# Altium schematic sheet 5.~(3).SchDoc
size 420 x 297 mm
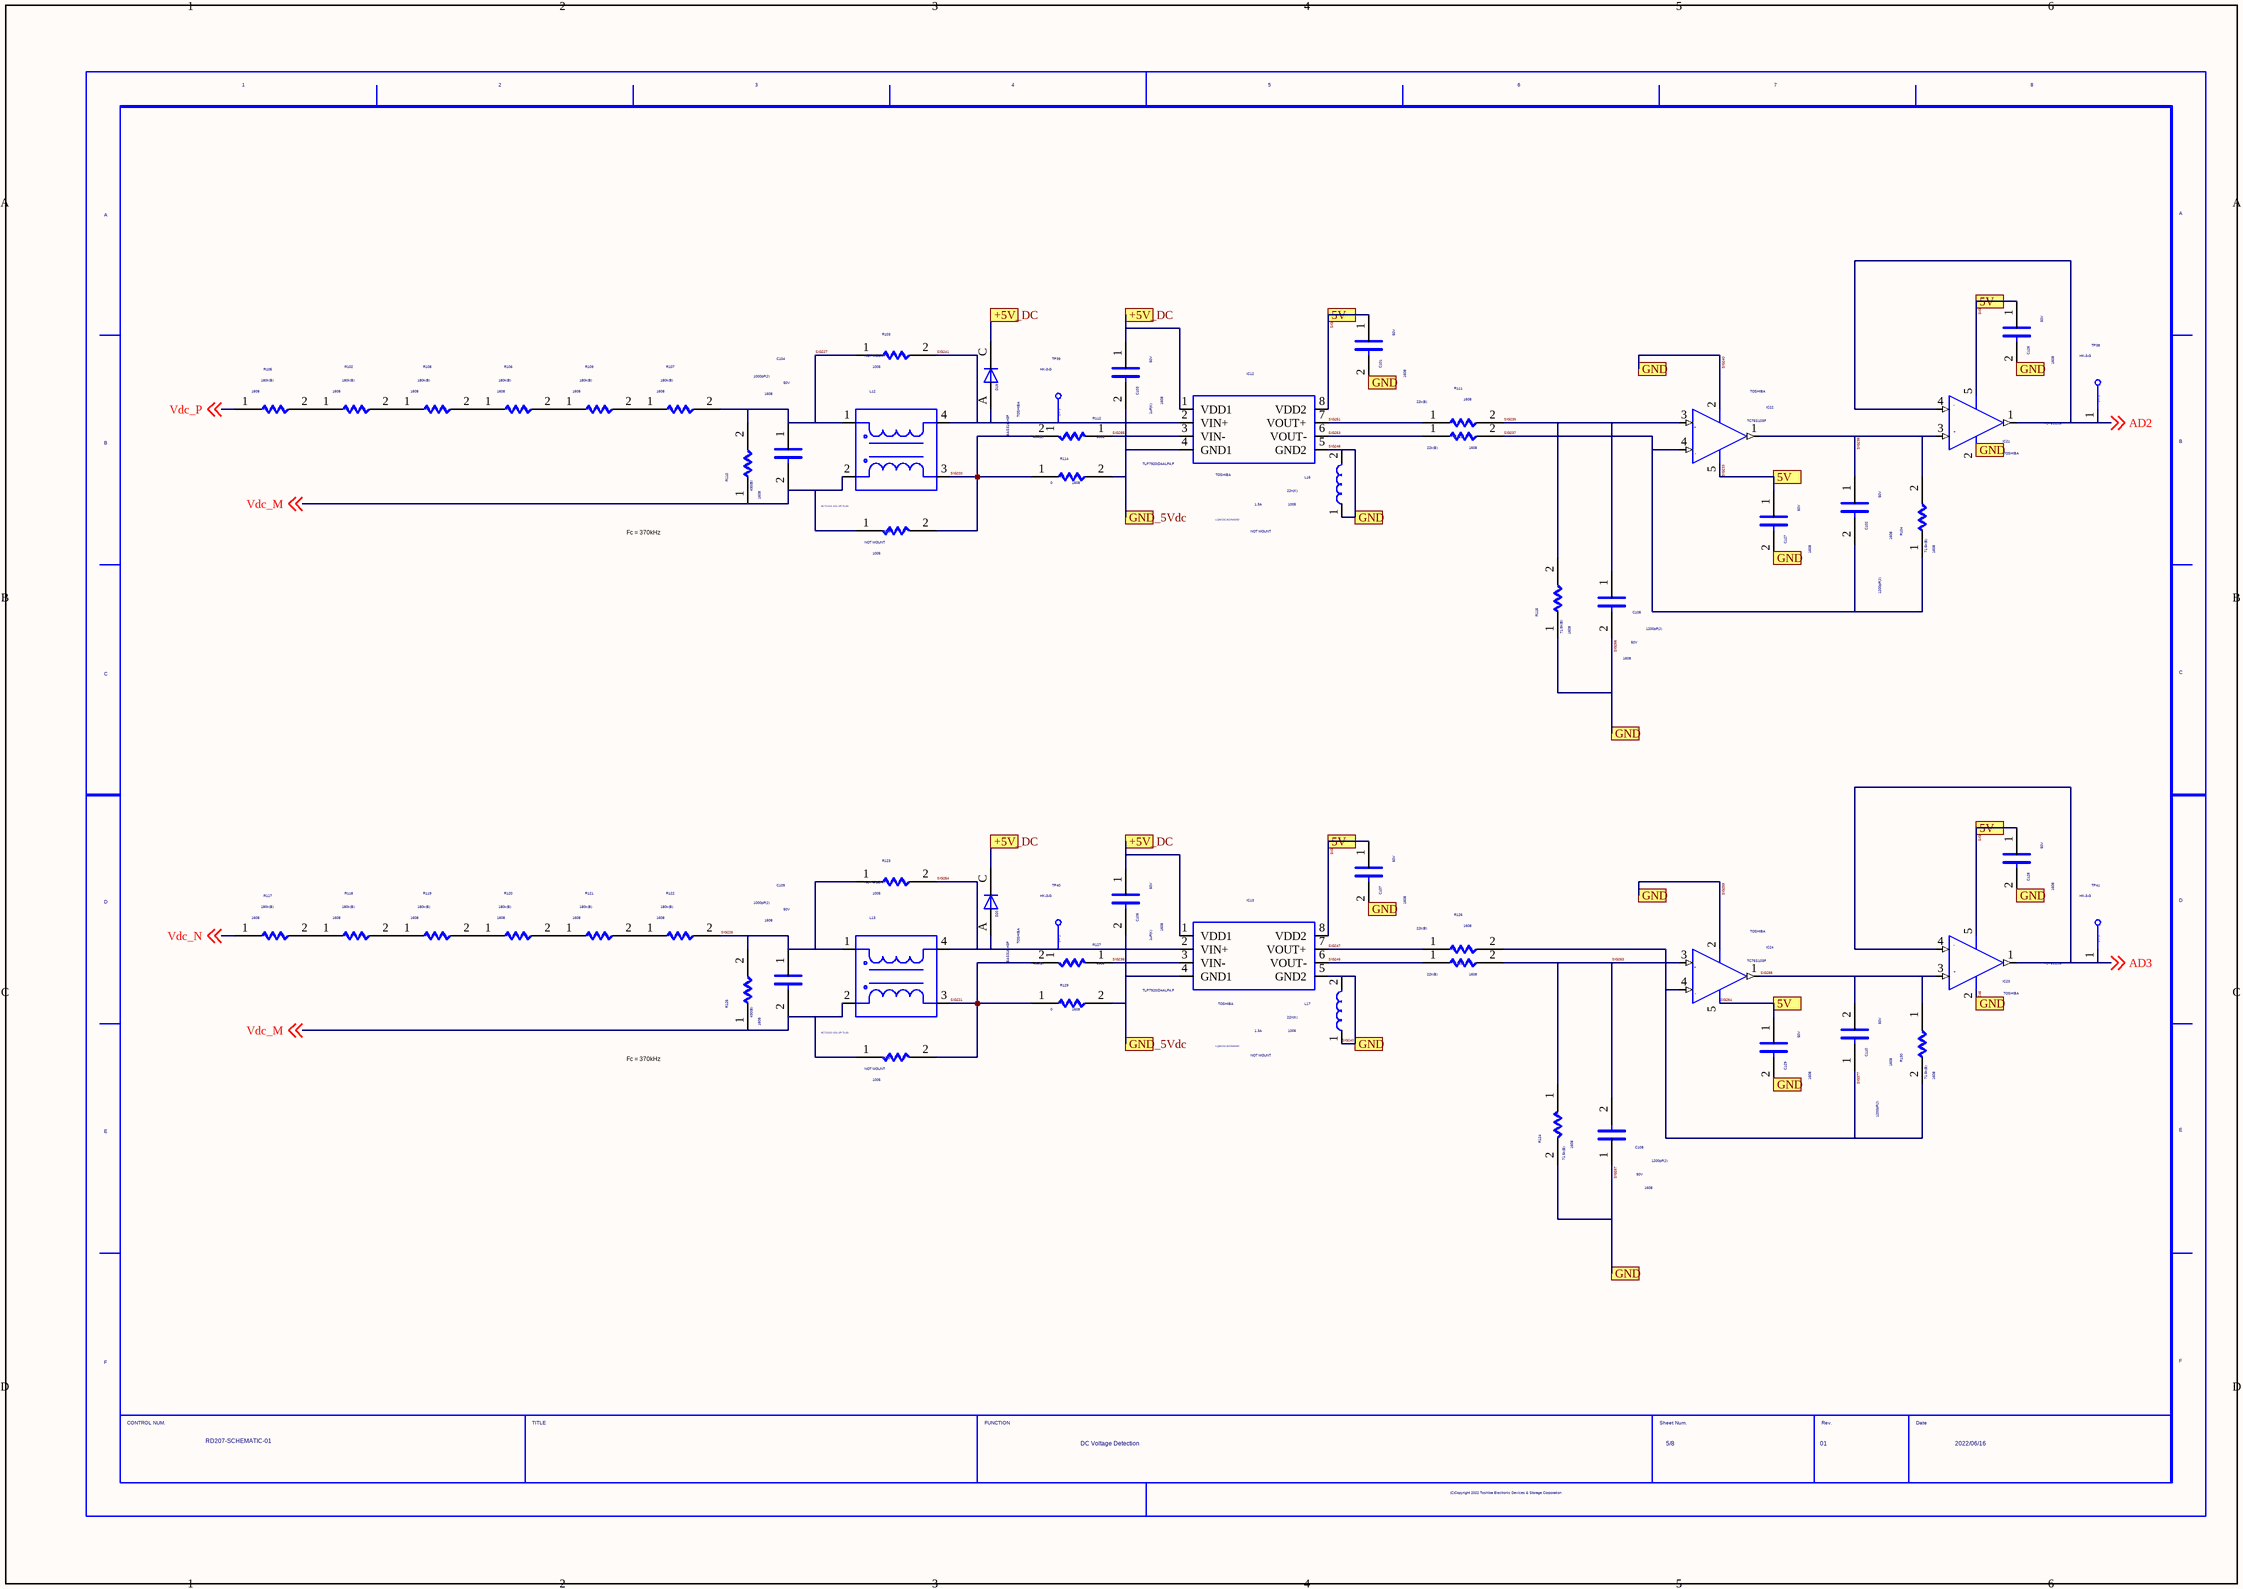
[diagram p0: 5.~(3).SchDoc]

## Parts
C101  SIZECODESMD: 1608  VAL2: 50V  VAL1: 1uF(K)  (hidden comment: C)
C102  SIZECODESMD: 1608  VAL2: 50V  VAL1: 1200pF(J)  (hidden comment: C)
C103  SIZECODESMD: 1608  VAL2: 50V  VAL1: 1uF(K)  (hidden comment: C)
C104  SIZECODESMD: 1608  VAL2: 50V  VAL1: 1000pF(J)  (hidden comment: C)
C105  SIZECODESMD: 1608  VAL2: 50V  VAL1: 1200pF(J)  (hidden comment: C)
C106  SIZECODESMD: 1608  VAL2: 50V  VAL1: 1uF(K)  (hidden comment: C)
C107  SIZECODESMD: 1608  VAL2: 50V  VAL1: 1uF(K)  (hidden comment: C)
C108  SIZECODESMD: 1608  VAL2: 50V  VAL1: 1200pF(J)  (hidden comment: C)
C109  SIZECODESMD: 1608  VAL2: 50V  VAL1: 1000pF(J)  (hidden comment: C)
C110  SIZECODESMD: 1608  VAL2: 50V  VAL1: 1200pF(J)  (hidden comment: C)
C126  SIZECODESMD: 1608  VAL2: 50V  VAL1: 1uF(K)  (hidden comment: C)
C127  SIZECODESMD: 1608  VAL2: 50V  VAL1: 1uF(K)  (hidden comment: C)
C128  SIZECODESMD: 1608  VAL2: 50V  VAL1: 1uF(K)  (hidden comment: C)
C129  SIZECODESMD: 1608  VAL2: 50V  VAL1: 1uF(K)  (hidden comment: C)
D19  USERCOMPTEXT3: TOSHIBA  VAL3: BAS316,H3F  (hidden comment: D)
D20  USERCOMPTEXT3: TOSHIBA  VAL3: BAS316,H3F  (hidden comment: D)
IC12  USERCOMPTEXT3: TOSHIBA  VAL3: TLP7920(D4ALF4,F  (hidden comment: TLP7920(D4ALF1,F)
IC13  USERCOMPTEXT3: TOSHIBA  VAL3: TLP7920(D4ALF4,F  (hidden comment: TLP7920(D4ALF1,F)
IC21  USERCOMPTEXT3: TOSHIBA  (hidden comment: TC75S103F)
IC22  USERCOMPTEXT3: TOSHIBA  (hidden comment: TC75S103F)
IC23  USERCOMPTEXT3: TOSHIBA  (hidden comment: TC75S103F)
IC24  USERCOMPTEXT3: TOSHIBA  (hidden comment: TC75S103F)
L12  ACT1210-101-2P-TL00
L13  ACT1210-101-2P-TL00
L16  NOTMOUNT: NOT MOUNT  VAL3: LQW15CA22NK00D  VAL2: 1.3A  VAL1: 22n(K)  SIZECODESMD: 1005  (hidden comment: L)
L17  NOTMOUNT: NOT MOUNT  VAL3: LQW15CA22NK00D  VAL2: 1.3A  VAL1: 22n(K)  SIZECODESMD: 1005  (hidden comment: L)
R102  SIZECODESMD: 1608  VAL1: 180k(B)  (hidden comment: R)
R103  SIZECODESMD: 1005  NOTMOUNT: NOT MOUNT  (hidden comment: R)
R104  SIZECODESMD: 1608  VAL1: 71.5k(B)  (hidden comment: R)
R105  SIZECODESMD: 1608  VAL1: 180k(B)  (hidden comment: R)
R106  SIZECODESMD: 1608  VAL1: 180k(B)  (hidden comment: R)
R107  SIZECODESMD: 1608  VAL1: 180k(B)  (hidden comment: R)
R108  SIZECODESMD: 1608  VAL1: 180k(B)  (hidden comment: R)
R109  SIZECODESMD: 1608  VAL1: 180k(B)  (hidden comment: R)
R110  SIZECODESMD: 1608  VAL1: 430(B)  (hidden comment: R)
R111  SIZECODESMD: 1608  VAL1: 22k(B)  (hidden comment: R)
R112  SIZECODESMD: 1608  VAL1: 430(B)  (hidden comment: R)
R113  SIZECODESMD: 1608  VAL1: 22k(B)  (hidden comment: R)
R114  SIZECODESMD: 1608  VAL1: 0  (hidden comment: R)
R115  SIZECODESMD: 1608  VAL1: 71.5k(B)  (hidden comment: R)
R116  SIZECODESMD: 1005  NOTMOUNT: NOT MOUNT  (hidden comment: R)
R117  SIZECODESMD: 1608  VAL1: 180k(B)  (hidden comment: R)
R118  SIZECODESMD: 1608  VAL1: 180k(B)  (hidden comment: R)
R119  SIZECODESMD: 1608  VAL1: 180k(B)  (hidden comment: R)
R120  SIZECODESMD: 1608  VAL1: 180k(B)  (hidden comment: R)
R121  SIZECODESMD: 1608  VAL1: 180k(B)  (hidden comment: R)
R122  SIZECODESMD: 1608  VAL1: 180k(B)  (hidden comment: R)
R123  SIZECODESMD: 1005  NOTMOUNT: NOT MOUNT  (hidden comment: R)
R124  SIZECODESMD: 1608  VAL1: 71.5k(B)  (hidden comment: R)
R125  SIZECODESMD: 1608  VAL1: 430(B)  (hidden comment: R)
R126  SIZECODESMD: 1608  VAL1: 22k(B)  (hidden comment: R)
R127  SIZECODESMD: 1608  VAL1: 430(B)  (hidden comment: R)
R128  SIZECODESMD: 1608  VAL1: 22k(B)  (hidden comment: R)
R129  SIZECODESMD: 1608  VAL1: 0  (hidden comment: R)
R130  SIZECODESMD: 1608  VAL1: 71.5k(B)  (hidden comment: R)
R131  SIZECODESMD: 1005  NOTMOUNT: NOT MOUNT  (hidden comment: R)
TP38  VAL3: HK-3-G  (hidden comment: TP)
TP39  VAL3: HK-3-G  (hidden comment: TP)
TP40  VAL3: HK-3-G  (hidden comment: TP)
TP41  VAL3: HK-3-G  (hidden comment: TP)
U?  DATE: 2022/06/16  REVISION: 01  SHEETNUMBER: 5/8  FUNCTION: DC Voltage Detection  DRAWINGNUMBER: RD207-SCHEMATIC-01  (hidden comment: WAKU_DEF100)

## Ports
5V, +5V_DC, GND, GND_5Vdc

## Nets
+5V_DC: C103.1 C106.1 D19.C D20.C IC12.1(VDD1) IC13.1(VDD1) ; port +5V_DC
AD2: IC21.1 IC21.4 TP38.1 ; off-sheet AD2
AD3: IC23.1 IC23.4 TP41.1 ; off-sheet AD3
GND_5Vdc: C103.2 C106.2 IC12.4(GND1) IC13.4(GND1) R114.2 R129.2 ; port GND_5Vdc
SIG220: L12.3 R112.2 R114.1 R116.2
SIG221: L13.3 R127.2 R129.1 R131.2
SIG225: C101.1 C107.1 C126.1 C127.1 C128.1 C129.1 IC12.8(VDD2) IC13.8(VDD2) IC21.5 IC22.5 IC23.5 IC24.5 ; port 5V  [also labelled SIG229, SIG233, SIG242, SIG252, SIG264]
SIG226: C109.1 L13.1 R122.2 R123.1 R125.2
SIG227: C104.1 L12.1 R103.1 R107.2 R110.2
SIG235: C102.1 IC21.3 IC22.1 R104.2
SIG236: IC13.3(VIN-) R127.1
SIG237: C102.2 IC22.4 R104.1 R113.2
SIG239: C105.1 IC22.3 R111.2 R115.2
SIG240: C101.2 C105.2 C107.2 C108.1 C126.2 C127.2 C128.2 C129.2 IC12.5(GND2) IC13.5(GND2) IC21.2 IC22.2 IC23.2 IC24.2 L16.1 L16.2 L17.1 L17.2 R115.1 R124.2 ; port GND  [also labelled SIG243, SIG245, SIG248, SIG259, SIG266, SIG267]
SIG241: D19.A IC12.2(VIN+) L12.4 R103.2 TP39.1
SIG246: IC13.6(VOUT-) R128.1
SIG247: IC13.7(VOUT+) R126.1
SIG251: IC12.7(VOUT+) R111.1
SIG253: IC12.6(VOUT-) R113.1
SIG254: D20.A IC13.2(VIN+) L13.4 R123.2 TP40.1
SIG255: C110.2 IC23.3 IC24.1 R130.1
SIG263: C108.2 IC24.3 R124.1 R128.2
SIG265: IC12.3(VIN-) R112.1
SIG377: C110.1 IC24.4 R126.2 R130.2
Vdc_M: C104.2 C109.2 L12.2 L13.2 R110.1 R116.1 R125.1 R131.1 ; off-sheet Vdc_M
Vdc_N: R117.1 ; off-sheet Vdc_N
Vdc_P: R105.1 ; off-sheet Vdc_P
NetR102_1: R102.1 R105.2
NetR102_2: R102.2 R108.1
NetR106_1: R106.1 R108.2
NetR106_2: R106.2 R109.1
NetR107_1: R107.1 R109.2
NetR117_2: R117.2 R118.1
NetR118_2: R118.2 R119.1
NetR119_2: R119.2 R120.1
NetR120_2: R120.2 R121.1
NetR121_2: R121.2 R122.1

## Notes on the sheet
- Fc = 370kHz

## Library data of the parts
C101 C103 C106 C107 C126-C129 = C: OriginalSymbolOrigin: (2540,7620); COMP: -C-UMK107AB7105KA-T
C102 C105 C108 = C: OriginalSymbolOrigin: (2540,7620); COMP: -C-GRM1885C1H122JA01J
C104 C109 = C: OriginalSymbolOrigin: (2540,7620); COMP: -C-GRM1885C1H102JA01D
C110 = C#1: OriginalSymbolOrigin: (2540,7620); CaptureCellPackProp: C##1; COMP: -C-GRM1885C1H122JA01J
D19 D20 = D: SAVEAREA0: -225,-91,12804,7836; SAVECOUNT: 3; TIME: 14:49:55; UPDATEUSER: 19870035; UPDATETIME: 14:20:16; OriginalSymbolOrigin: (5080,5080); COMP: -D-BAS316_H3F_AC
IC12 IC13 = TLP7920_D4ALF4_F: Photocoupler; COMP: IC-TLP7920F_D4ALF4_F; TIME: 16:53:58; UPDATEUSER: t5459927; UPDATETIME: 15:20:44; SAVECOUNT: 3; SAVEAREA0: -6054,-17255,23482,4367; OriginalSymbolOrigin: (0,0)
IC21-IC24 = TC75S103F: COMP: IC-TC75S103F; TIME: 16:31:59; UPDATEUSER: t5459927; UPDATETIME: 13:42:20; SAVECOUNT: 13; SAVEAREA0: 0,-513,15240,10643; OriginalSymbolOrigin: (2540,10160)
L12 L13 = ACT1210_101_2P_TL00: 150mA; MAKER: TDK; COMP: -L-ACT1210-101-2P-TL00; NOTE: 100uH; TIME: 11:39:41; UPDATEUSER: t5459927; UPDATETIME: 16:14:20; SAVECOUNT: 2; SAVEAREA0: -3836,-15544,18561,852; OriginalSymbolOrigin: (0,0); VAL1: 100uH(Z)
L16 L17 = L: OriginalSymbolOrigin: (2540,5080); COMP: L-NC_LQW15CA22NK00D
R102 R105-R109 R117-R122 = R: OriginalSymbolOrigin: (5080,5080); COMP: -R-ERA3AEB184V; VAL2: 100mW
R103 R116 R123 R131 = R: OriginalSymbolOrigin: (5080,5080); COMP: -R-NC_R1005
R104 R115 R124 = R: OriginalSymbolOrigin: (5080,5080); COMP: -R-ERA3AEB7152V; VAL2: 100mW
R110 R112 R125 R127 = R: OriginalSymbolOrigin: (5080,5080); COMP: -R-ERA3AEB431V; VAL2: 100mW
R111 R113 R126 R128 = R: OriginalSymbolOrigin: (5080,5080); COMP: -R-ERA3AEB223V; VAL2: 100mW
R114 R129 = R: OriginalSymbolOrigin: (5080,5080); COMP: -R-RK73Z1JTTD; VAL2: 1A
R130 = R#1: OriginalSymbolOrigin: (5080,5080); CaptureCellPackProp: R##1; COMP: -R-ERA3AEB7152V; VAL2: 100mW
TP38-TP41 = TP: TIME: 16:12:21; UPDATEUSER: fukuda-y; UPDATETIME: 16:18:11; SAVECOUNT: 2; SAVEAREA0: -242,-92,12810,7836; OriginalSymbolOrigin: (0,7620); COMP: -TP-HK-3-G
U? = WAKU_DEF100: PLOTTIME: HH:MM; SAVEAREA0: 22200,72372,612276,319236; TIME: 14:30:25; UPDATEUSER: t5459927; UPDATETIME: 09:21:32; SAVECOUNT: 7; OriginalSymbolOrigin: (10160,284480)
